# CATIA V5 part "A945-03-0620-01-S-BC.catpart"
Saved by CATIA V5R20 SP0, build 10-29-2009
Part number: A945-03-0620-01-S-BC
Source: Unknown
Property "ARTICLENO": "A945-03-0620-01-S-BC"
Property "B": "65.000"
Property "BOMINFO": "A945-03-0620-01-S-BC"
Property "CODE": "A945-03-0620-01-S-BC"
Property "D1": "20.000"
Property "D2": "13.500"
Property "D5": "16.000"
Property "D6": "12.000"
Property "H": "47.000"
Property "H1": "34.000"
Property "H2": "35.000"
Property "H3": "18.000"
Property "L1": "200.000"
Property "L2": "25.000"
Property "L3": "0.000"
Property "L4": "150.000"
Property "L5": "55.000"
Property "L6": "95.000"
Property "LINA": "A945-03-0620-01-S-BC"
Property "N": "2.000"
Property "NB": "A945-03-0620-01-S-BC"
Property "NBSYN": "$CODE."
Property "NN": "A945-03"
Property "NT": "v driver sets replaceable inserts pisitive return"
Property "SUPPLIER": "CF"
Property "Z": "65.000"
Bounding box of the stored display mesh (mm): x -5049.207 to -4951.207, y -575.36 to -510.36, z 0 to 200
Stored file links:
  C:\Users\Utente\Desktop\3D files A945-03\A945-03-0620-01-S-BC.catpart
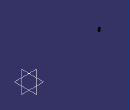
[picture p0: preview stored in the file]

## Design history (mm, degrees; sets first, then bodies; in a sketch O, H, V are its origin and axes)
Body1 "Geometry.1" (main body)
  Solid1 "A945-03-0620-01-S-BC.catpart": solid without history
